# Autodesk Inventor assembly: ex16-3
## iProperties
Shininess: 64.0
Length Units: 11269
Angle Units: 11279
Time Units: 11290
Mass Units: 11283
Length Display Precision: 3
Angle Display Precision: 2
Compacted: True
Created: 2002-11
Part Number: ex16-3
Document SubType Name: Assembly
Designer: E. MOSS
Density: 0.0
Volumn: 0.0
Area: 0.0
PropertySet Name: Model Information
Control State: 0
Master: False
Checked Out: False
Author: E. MOSS
